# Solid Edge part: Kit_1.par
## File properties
Sűrűség: 0,000 kg/m^3
Pontosság: 0,990
Author: bmolnar
Last saved by: bmolnar
Revision: 77
Username: bmolnar
Dokumentum tartalom típus: 0
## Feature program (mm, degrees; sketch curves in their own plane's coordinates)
base feature "unnamed BaseFeature 1"
sketch for "unnamed Cutout 1" plane through (0, -0.0012, 85.05) normal (0, 0, -1) x-axis (-1, 0, 0)
  circle centre (0, 0.0012) radius 6
extrude "unnamed Cutout 1" cut through along -normal
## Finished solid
Body 1: solid body, 48 faces, 65 edges, 51 vertices, 1 internal void.
  Faces by surface: cone 15, cylinder 15, plane 14, torus 4
  Edges by curve: circle 47, line 18
Bounding box of the edges (mm; curved faces can reach further): 35.700 x 35.450 x 9.450, from (-17.85, -16.85, 85.05) to (17.85, 18.6, 94.5).
Cylindrical faces by radius (mm): R1.25 x2, R2.25 x2, R6 x1, R6.27 x1, R6.85 x1, R7 x1, R8.16 x1, R8.25 x1, R11.5 x1, R12.25 x1, R15.9 x1, R16.85 x1, R17.85 x1
Conical faces (half-angle, radius in mm at the cone's reference point): 3 deg R8.205 x1, 7 deg R7.5925 x1, 14 deg R6.135 x1, 14 deg R6.4811 x1, 17 deg R6.135 x1, 23 deg R6.829 x1, 30 deg R11.875 x1, 42.5 deg R6.1233 x1, 45 deg R7.1 x2, 45 deg R11.75 x1, 84 deg R59.397 x2, 85 deg R7.9463 x1, 87 deg R6.1765 x1
Toroidal faces (ring radius, tube radius in mm): R6.8057 r0.2025 x1, R7.2522 r0.2925 x1, R7.96 r0.2 x1, R11.9 r0.4 x1
Planar faces by outward normal: +z 7, -z 3, oblique 4
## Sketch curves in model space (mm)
circle centre (0, 0, 85.05) radius 6
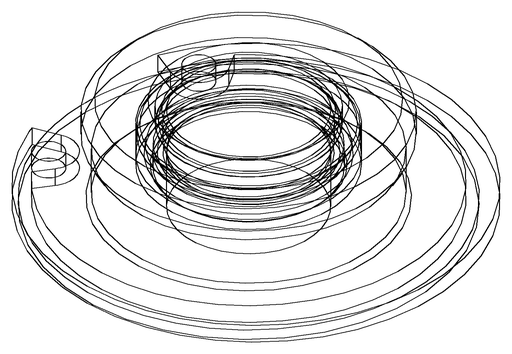
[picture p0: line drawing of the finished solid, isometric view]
